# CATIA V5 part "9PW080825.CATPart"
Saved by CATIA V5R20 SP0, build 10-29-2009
Part number: 9PW080825
Revision: ANY
Definition: UNKNOWN
Nomenclature: 9PW080825
Source: Unknown
Bounding box of the stored display mesh (mm): x -139.513 to 0, y -11.973 to 4, z -4.1 to 4.1
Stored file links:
  C:\Users\Utente\Desktop\IO LAVORO\3D X SITO CF\CUMSA\3D files PW\pw080825\pw080825_ejection\9PW080825.CATPart
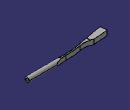
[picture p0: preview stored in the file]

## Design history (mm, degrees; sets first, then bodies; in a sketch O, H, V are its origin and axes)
Body1 "Chaflán3" (main body)
  Solid1: solid without history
